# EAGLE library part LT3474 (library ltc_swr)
LT3474 - Step-Down 1A LED Driver True Color PWM Delivers Constant Color with 400:1 Dimming Range Wide Input Range: 4V to 36V Up to 1A LED Current Adjustable 200kHz&ndash;2MHz Switching Frequency Adjustable Control of LED Current Integrated Boost Diode High Output Current Accuracy is Maintained Over a Wide Range from 35mA to 1A Open LED and Short-Circuit Protection High Side Sense Allows Grounded Cathode Connection Uses Small Inductors and Ceramic Capacitors Compact 16-Lead TSSOP Thermally Enhanced Surface Mount Package
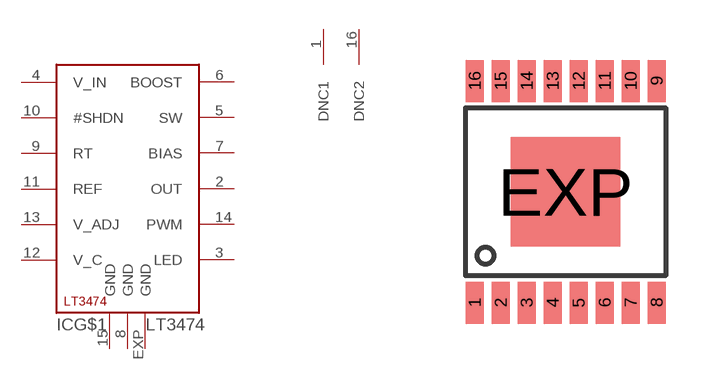
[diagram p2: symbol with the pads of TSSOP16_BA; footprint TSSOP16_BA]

Designator prefix IC; gates G$1=LT3474 G$2=LT3475_SUP G$3=LT3475_SUP G$4=LT3474_DNC

## LT3474  [TSSOP16_BA]
1  G$4:DNC1  nc
2  G$1:OUT  pas
3  G$1:LED  pas
4  G$1:V_IN  pas
5  G$1:SW  pas
6  G$1:BOOST  pas
7  G$1:BIAS  pas
8  G$1:GND  pwr
9  G$1:RT  pas
10  G$1:#SHDN  pas
11  G$1:REF  pas
12  G$1:V_C  pas
13  G$1:V_ADJ  pas
14  G$1:PWM  pas
15  G$2:GND  pwr
16  G$4:DNC2  nc
EXP  G$3:GND  pwr

## Footprint TSSOP16_BA (pad centres in mm)
smd 0.45 x 1.05: 1 -2.275,-2.775; 2 -1.625,-2.775; 3 -0.975,-2.775; 4 -0.325,-2.775; 5 0.325,-2.775; 6 0.975,-2.775; 7 1.625,-2.775; 8 2.275,-2.775; 9 2.275,2.775; 10 1.625,2.775; 11 0.975,2.775; 12 0.325,2.775; 13 -0.325,2.775; 14 -0.975,2.775; 15 -1.625,2.775; 16 -2.275,2.775
smd 2.74 x 2.74: EXP 0,0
